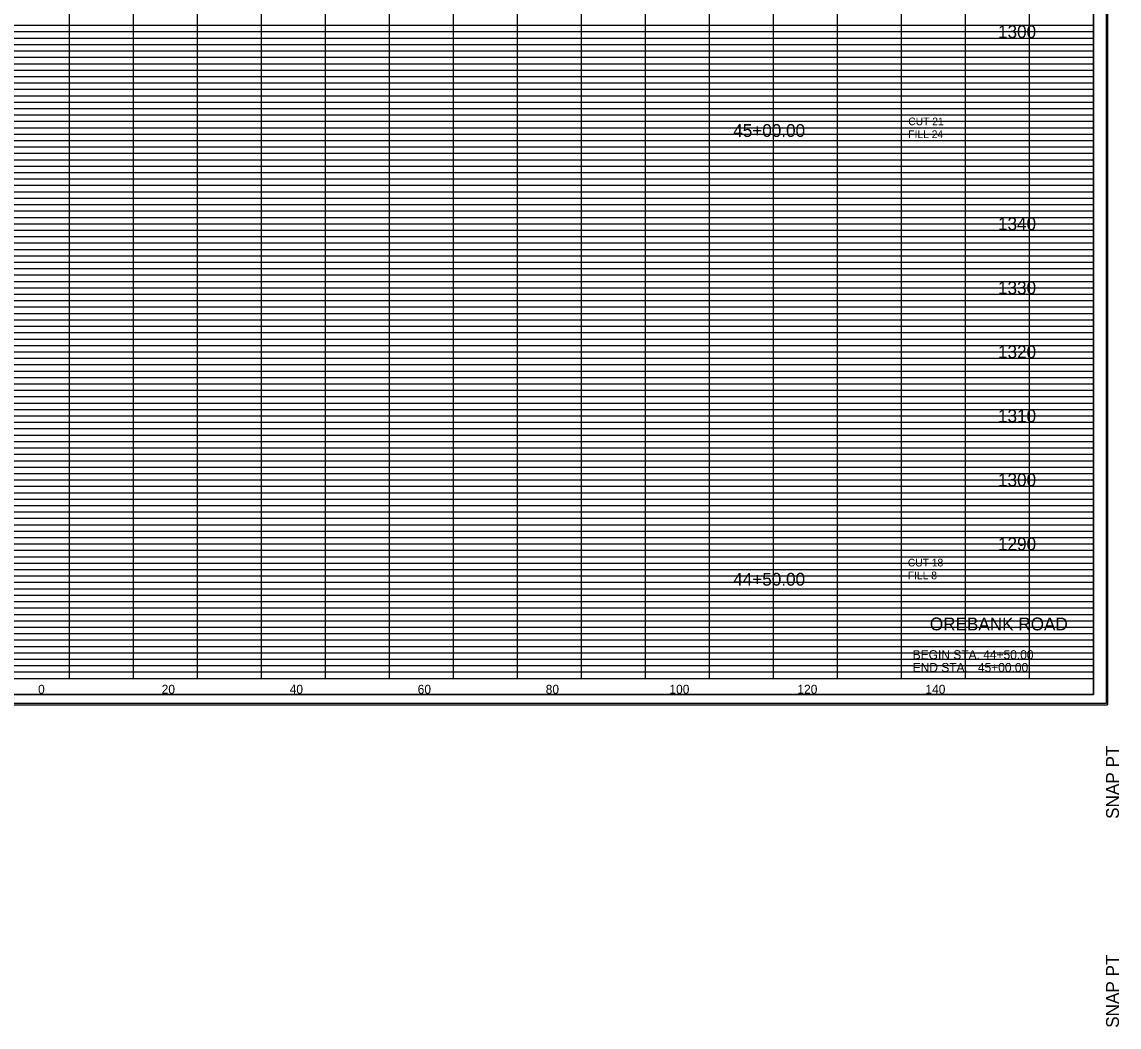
# Model space of a CAD drawing. Extents: x 980 to 1324, y 978 to 2847.
# Drawn here: x 1152.6 to 1324, y 1485.5 to 1642.5 of the extents above; entities that cross this region are included whole.
import ezdxf

# ---------------------------------------------------------------- set-up
doc = ezdxf.new("R2010")
doc.units = 0
for name, color, linetype in [('DESIGN - SHEET - Corner Text', 7, 'Continuous'), ('DESIGN - SHEET - Light Grid', 7, 'Continuous'), ('DESIGN - SHEET - Linework', 7, 'Continuous'), ('DESIGN - SHEET - Plot Shape', 7, 'Continuous'), ('DESIGN - TYPICAL - Text', 7, 'Continuous')]:
    doc.layers.add(name, color=color, linetype=linetype)

# ---------------------------------------------------------------- blocks, each defined once
blk = doc.blocks.new('XSTSHT')
at = {"layer": 'DESIGN - SHEET - Light Grid'}
for p, q in [((8, 10.2), (16, 10.2)), ((16, 10.2), (24, 10.2)), ((24, 10.2), (32, 10.2)), ((8, 10.1), (16, 10.1)), ((16, 10.1), (24, 10.1)), ((24, 10.1), (32, 10.1)), ((8, 9.9), (16, 9.9)), ((8, 9.8), (16, 9.8)), ((16, 9.9), (24, 9.9)), ((16, 9.8), (24, 9.8)), ((24, 9.9), (32, 9.9)), ((24, 9.8), (32, 9.8)), ((8, 9.7), (16, 9.7)), ((8, 9.6), (16, 9.6)), ((16, 9.7), (24, 9.7)), ((16, 9.6), (24, 9.6)), ((24, 9.7), (32, 9.7)), ((24, 9.6), (32, 9.6)), ((8, 9.5), (16, 9.5)), ((16, 9.5), (24, 9.5)), ((24, 9.5), (32, 9.5)), ((8, 9.4), (16, 9.4)), ((8, 9.3), (16, 9.3)), ((16, 9.4), (24, 9.4)), ((16, 9.3), (24, 9.3)), ((24, 9.4), (32, 9.4)), ((24, 9.3), (32, 9.3)), ((8, 9.2), (16, 9.2)), ((8, 9.1), (16, 9.1)), ((16, 9.2), (24, 9.2)), ((16, 9.1), (24, 9.1)), ((24, 9.2), (32, 9.2)), ((24, 9.1), (32, 9.1)), ((8, 8.9), (16, 8.9)), ((8, 8.8), (16, 8.8)), ((16, 8.9), (24, 8.9)), ((16, 8.8), (24, 8.8)), ((24, 8.9), (32, 8.9)), ((24, 8.8), (32, 8.8)), ((8, 8.7), (16, 8.7)), ((8, 8.6), (16, 8.6)), ((16, 8.7), (24, 8.7)), ((16, 8.6), (24, 8.6)), ((24, 8.7), (32, 8.7)), ((24, 8.6), (32, 8.6)), ((8, 8.5), (16, 8.5)), ((8, 8.4), (16, 8.4)), ((16, 8.5), (24, 8.5)), ((16, 8.4), (24, 8.4)), ((24, 8.5), (32, 8.5)), ((24, 8.4), (32, 8.4)), ((8, 8.3), (16, 8.3)), ((16, 8.3), (24, 8.3)), ((24, 8.3), (32, 8.3)), ((8, 8.2), (16, 8.2)), ((8, 8.1), (16, 8.1)), ((16, 8.2), (24, 8.2)), ((16, 8.1), (24, 8.1)), ((24, 8.2), (32, 8.2)), ((24, 8.1), (32, 8.1)), ((8, 7.9), (16, 7.9)), ((16, 7.9), (24, 7.9)), ((24, 7.9), (32, 7.9)), ((8, 7.8), (16, 7.8)), ((16, 7.8), (24, 7.8)), ((24, 7.8), (32, 7.8)), ((8, 7.7), (16, 7.7)), ((8, 7.6), (16, 7.6)), ((16, 7.7), (24, 7.7)), ((16, 7.6), (24, 7.6)), ((24, 7.7), (32, 7.7)), ((24, 7.6), (32, 7.6)), ((8, 7.5), (16, 7.5)), ((8, 7.4), (16, 7.4)), ((16, 7.5), (24, 7.5)), ((16, 7.4), (24, 7.4)), ((24, 7.5), (32, 7.5)), ((24, 7.4), (32, 7.4)), ((8, 7.3), (16, 7.3)), ((8, 7.2), (16, 7.2)), ((16, 7.3), (24, 7.3)), ((16, 7.2), (24, 7.2)), ((24, 7.3), (32, 7.3)), ((24, 7.2), (32, 7.2)), ((8, 7.1), (16, 7.1)), ((16, 7.1), (24, 7.1)), ((24, 7.1), (32, 7.1)), ((8, 6.9), (16, 6.9)), ((16, 6.9), (24, 6.9)), ((24, 6.9), (32, 6.9)), ((8, 6.8), (16, 6.8)), ((8, 6.7), (16, 6.7)), ((16, 6.8), (24, 6.8)), ((16, 6.7), (24, 6.7)), ((24, 6.8), (32, 6.8)), ((24, 6.7), (32, 6.7)), ((8, 6.6), (16, 6.6)), ((16, 6.6), (24, 6.6)), ((24, 6.6), (32, 6.6)), ((8, 6.5), (16, 6.5)), ((8, 6.4), (16, 6.4)), ((16, 6.5), (24, 6.5)), ((16, 6.4), (24, 6.4)), ((24, 6.5), (32, 6.5)), ((24, 6.4), (32, 6.4)), ((8, 6.3), (16, 6.3)), ((8, 6.2), (16, 6.2)), ((16, 6.3), (24, 6.3)), ((16, 6.2), (24, 6.2)), ((24, 6.3), (32, 6.3)), ((24, 6.2), (32, 6.2)), ((8, 6.1), (16, 6.1)), ((16, 6.1), (24, 6.1)), ((24, 6.1), (32, 6.1)), ((8, 5.9), (16, 5.9)), ((16, 5.9), (24, 5.9)), ((24, 5.9), (32, 5.9)), ((8, 5.8), (16, 5.8)), ((8, 5.7), (16, 5.7)), ((16, 5.8), (24, 5.8)), ((16, 5.7), (24, 5.7)), ((24, 5.8), (32, 5.8)), ((24, 5.7), (32, 5.7)), ((8, 5.6), (16, 5.6)), ((8, 5.5), (16, 5.5)), ((16, 5.6), (24, 5.6)), ((16, 5.5), (24, 5.5)), ((24, 5.6), (32, 5.6)), ((24, 5.5), (32, 5.5)), ((8, 5.4), (16, 5.4)), ((16, 5.4), (24, 5.4)), ((24, 5.4), (32, 5.4)), ((8, 5.3), (16, 5.3)), ((8, 5.2), (16, 5.2)), ((16, 5.3), (24, 5.3)), ((16, 5.2), (24, 5.2)), ((24, 5.3), (32, 5.3)), ((24, 5.2), (32, 5.2)), ((8, 5.1), (16, 5.1)), ((16, 5.1), (24, 5.1)), ((24, 5.1), (32, 5.1)), ((8, 4.9), (16, 4.9)), ((8, 4.8), (16, 4.8)), ((16, 4.9), (24, 4.9)), ((16, 4.8), (24, 4.8)), ((24, 4.9), (32, 4.9)), ((24, 4.8), (32, 4.8)), ((8, 4.7), (16, 4.7)), ((16, 4.7), (24, 4.7)), ((24, 4.7), (32, 4.7)), ((8, 4.6), (16, 4.6)), ((8, 4.5), (16, 4.5)), ((16, 4.6), (24, 4.6)), ((16, 4.5), (24, 4.5)), ((24, 4.6), (32, 4.6)), ((24, 4.5), (32, 4.5)), ((8, 4.4), (16, 4.4)), ((8, 4.3), (16, 4.3)), ((16, 4.4), (24, 4.4)), ((16, 4.3), (24, 4.3)), ((24, 4.4), (32, 4.4)), ((24, 4.3), (32, 4.3)), ((8, 4.2), (16, 4.2)), ((16, 4.2), (24, 4.2)), ((24, 4.2), (32, 4.2)), ((8, 4.1), (16, 4.1)), ((16, 4.1), (24, 4.1)), ((24, 4.1), (32, 4.1)), ((8, 3.9), (16, 3.9)), ((8, 3.8), (16, 3.8)), ((16, 3.9), (24, 3.9)), ((16, 3.8), (24, 3.8)), ((24, 3.9), (32, 3.9)), ((24, 3.8), (32, 3.8)), ((8, 3.7), (16, 3.7)), ((8, 3.6), (16, 3.6)), ((16, 3.7), (24, 3.7)), ((16, 3.6), (24, 3.6)), ((24, 3.7), (32, 3.7)), ((24, 3.6), (32, 3.6)), ((8, 3.5), (16, 3.5)), ((16, 3.5), (24, 3.5)), ((24, 3.5), (32, 3.5)), ((8, 3.4), (16, 3.4)), ((8, 3.3), (16, 3.3)), ((16, 3.4), (24, 3.4)), ((16, 3.3), (24, 3.3)), ((24, 3.4), (32, 3.4)), ((24, 3.3), (32, 3.3)), ((8, 3.2), (16, 3.2)), ((8, 3.1), (16, 3.1)), ((16, 3.2), (24, 3.2)), ((16, 3.1), (24, 3.1)), ((24, 3.2), (32, 3.2)), ((24, 3.1), (32, 3.1)), ((8, 2.9), (16, 2.9)), ((8, 2.8), (16, 2.8)), ((16, 2.9), (24, 2.9)), ((16, 2.8), (24, 2.8)), ((24, 2.9), (32, 2.9)), ((24, 2.8), (32, 2.8)), ((8, 2.7), (16, 2.7)), ((8, 2.6), (16, 2.6)), ((16, 2.7), (24, 2.7)), ((16, 2.6), (24, 2.6)), ((24, 2.7), (32, 2.7)), ((24, 2.6), (32, 2.6)), ((8, 2.5), (16, 2.5)), ((8, 2.4), (16, 2.4)), ((16, 2.5), (24, 2.5)), ((16, 2.4), (24, 2.4)), ((24, 2.5), (32, 2.5)), ((24, 2.4), (32, 2.4)), ((8, 2.3), (16, 2.3)), ((16, 2.3), (24, 2.3)), ((24, 2.3), (32, 2.3)), ((8, 2.2), (16, 2.2)), ((8, 2.1), (16, 2.1)), ((16, 2.2), (24, 2.2)), ((16, 2.1), (24, 2.1)), ((24, 2.2), (32, 2.2)), ((24, 2.1), (32, 2.1)), ((8, 1.9), (16, 1.9)), ((16, 1.9), (24, 1.9)), ((24, 1.9), (32, 1.9)), ((8, 1.8), (16, 1.8)), ((16, 1.8), (24, 1.8)), ((24, 1.8), (32, 1.8)), ((8, 1.7), (16, 1.7)), ((8, 1.6), (16, 1.6)), ((16, 1.7), (24, 1.7)), ((16, 1.6), (24, 1.6)), ((24, 1.7), (32, 1.7)), ((24, 1.6), (32, 1.6)), ((8, 1.5), (16, 1.5)), ((8, 1.4), (16, 1.4)), ((16, 1.5), (24, 1.5)), ((16, 1.4), (24, 1.4)), ((24, 1.5), (32, 1.5)), ((24, 1.4), (32, 1.4)), ((8, 1.3), (16, 1.3)), ((8, 1.2), (16, 1.2)), ((16, 1.3), (24, 1.3)), ((16, 1.2), (24, 1.2)), ((24, 1.3), (32, 1.3)), ((24, 1.2), (32, 1.2)), ((8, 1.1), (16, 1.1)), ((16, 1.1), (24, 1.1)), ((24, 1.1), (32, 1.1)), ((8, 0.9), (16, 0.9)), ((16, 0.9), (24, 0.9)), ((24, 0.9), (32, 0.9)), ((8, 0.8), (16, 0.8)), ((8, 0.7), (16, 0.7)), ((16, 0.8), (24, 0.8)), ((16, 0.7), (24, 0.7)), ((24, 0.8), (32, 0.8)), ((24, 0.7), (32, 0.7)), ((8, 0.6), (16, 0.6)), ((16, 0.6), (24, 0.6)), ((24, 0.6), (32, 0.6)), ((8, 0.5), (16, 0.5)), ((8, 0.4), (16, 0.4)), ((16, 0.5), (24, 0.5)), ((16, 0.4), (24, 0.4)), ((24, 0.5), (32, 0.5)), ((24, 0.4), (32, 0.4)), ((8, 0.3), (16, 0.3)), ((8, 0.2), (16, 0.2)), ((16, 0.3), (24, 0.3)), ((16, 0.2), (24, 0.2)), ((24, 0.3), (32, 0.3)), ((24, 0.2), (32, 0.2)), ((8, 0.1), (16, 0.1)), ((16, 0.1), (24, 0.1)), ((24, 0.1), (32, 0.1))]:
    blk.add_line(p, q, dxfattribs=at)
at = {"layer": 'DESIGN - SHEET - Linework'}
for p, q in [((32.217, 21.414), (32.217, -0.414)), ((16, 0), (16, 21)), ((17, 0), (17, 21)), ((18, 0), (18, 21)), ((19, 0), (19, 21)), ((20, 0), (20, 21)), ((21, 0), (21, 21)), ((22, 0), (22, 21)), ((23, 0), (23, 21)), ((24, 0), (24, 21)), ((25, 0), (25, 21)), ((26, 0), (26, 21)), ((27, 0), (27, 21)), ((28, 0), (28, 20)), ((29, 0), (29, 20)), ((30, 0), (30, 20)), ((31, 0), (31, 20)), ((0, 10), (32, 10)), ((0, 9), (32, 9)), ((0, 8), (32, 8)), ((0, 7), (32, 7)), ((0, 6), (32, 6)), ((0, 5), (32, 5)), ((0, 4), (32, 4)), ((0, 3), (32, 3)), ((0, 2), (32, 2)), ((0, 1), (32, 1)), ((-1.823, -0.414), (32.217, -0.414))]:
    blk.add_line(p, q, dxfattribs=at)
blk.add_lwpolyline([(0, 21), (0, 0), (32, 0), (32, 21), (0, 21)], dxfattribs=at)
at = {"layer": 'DESIGN - SHEET - Plot Shape'}
for points in [[(-1.803, 21.394), (32.197, 21.394), (32.197, -0.394), (-1.803, -0.394)], [(-0.85, 21), (32, 21), (32, -0.25), (-0.85, -0.25)]]:
    blk.add_lwpolyline(points, close=True, dxfattribs=at)
at = {"layer": 'DESIGN - SHEET - Corner Text'}
for s, p in [('  SNAP PT', (32.397, 21.394)), ('SNAP PT  ', (32.397, -2.194))]:
    blk.add_text(s, height=0.2, rotation=90, dxfattribs=at).set_placement(p)

msp = doc.modelspace()

# ---------------------------------------------------------------- linework, layer by layer
at = {"layer": 'DESIGN - SHEET - Plot Shape'}
msp.add_lwpolyline([(991.5, 1537.5), (1320, 1537.5), (1320, 1750), (991.5, 1750)], close=True, dxfattribs=at)

# ---------------------------------------------------------------- block references
at = {"layer": 'DESIGN - SHEET - Plot Shape', "xscale": 10, "yscale": 10}
for p in [(1000, 1540), (1000, 1270)]:
    msp.add_blockref('XSTSHT', p, dxfattribs=at)

# ---------------------------------------------------------------- texts
at = {"layer": 'DESIGN - SHEET - Corner Text'}
for s, height, p in [('OREBANK ROAD', 2, (1294.44, 1547.5)), ('BEGIN STA. 44+50.00', 1.4, (1291.75, 1543)), ('END STA.   45+00.00', 1.4, (1291.75, 1541))]:
    msp.add_text(s, height=height, dxfattribs=at).set_placement(p)
at = {"layer": 'DESIGN - TYPICAL - Text'}
for s, height, p in [('     1300     ', 2, (1301.37, 1640)), ('CUT 21', 1.2, (1291.07, 1626.38)), ('     45+00.00     ', 2, (1260, 1624.56)), ('FILL 24', 1.2, (1291.07, 1624.38)), ('     1340     ', 2, (1301.37, 1610)), ('     1330     ', 2, (1301.37, 1600)), ('     1320     ', 2, (1301.37, 1590)), ('     1310     ', 2, (1301.37, 1580)), ('     1300     ', 2, (1301.37, 1570)), ('     1290     ', 2, (1301.37, 1560)), ('CUT 18', 1.2, (1291, 1557.48)), ('     44+50.00     ', 2, (1260, 1554.48)), ('FILL 8', 1.2, (1291, 1555.48)), ('     0     ', 1.4, (1152.51, 1537.6)), ('     0     ', 1.4, (1152.51, 1537.6)), ('     20     ', 1.4, (1171.82, 1537.6)), ('     40     ', 1.4, (1191.82, 1537.6)), ('     60     ', 1.4, (1211.82, 1537.6)), ('     80     ', 1.4, (1231.82, 1537.6)), ('     100     ', 1.4, (1251.14, 1537.6)), ('     120     ', 1.4, (1271.14, 1537.6)), ('     140     ', 1.4, (1291.14, 1537.6))]:
    msp.add_text(s, height=height, dxfattribs=at).set_placement(p)

doc.saveas('drawing.dxf')
